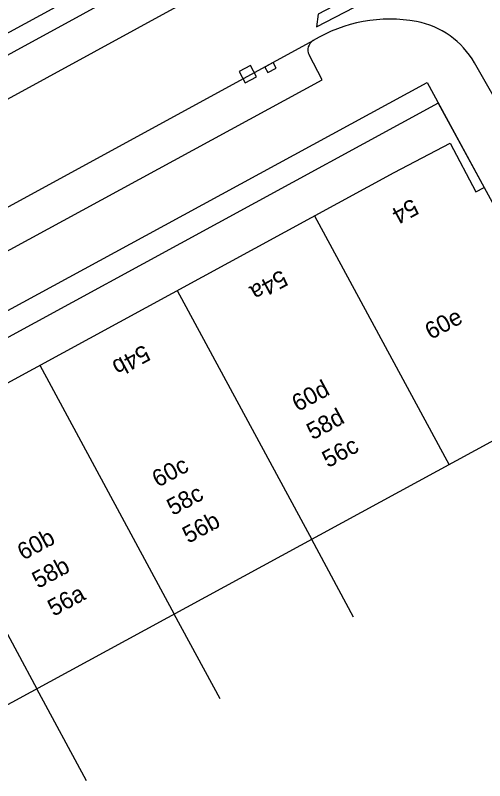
# Model space of a CAD drawing. Extents: x 81065 to 81486, y 452384 to 452681.
# Drawn here: x 81217.68 to 81239.76, y 452440.27 to 452476.31 of the extents above; entities that cross this region are included whole.
import ezdxf

# ---------------------------------------------------------------- set-up
doc = ezdxf.new("R2010")
doc.units = 0
for name, color, linetype in [('B-BH-AL-TOPOGRAFIE_HUISNUMMER-T25', 7, 'Continuous'), ('B-BH-OG-TERREIN_ERF-GV', 7, 'Continuous'), ('B-BH-OG-TOPOGRAFIE_BEBOUWING-GV', 7, 'Continuous'), ('B-BH-OG-TOPOGRAFIE_BEBOUWING_PANDSCHEIDING-GV', 7, 'Continuous'), ('B-BH-RI-GWA_RIOOLPUT-S', 7, 'Continuous'), ('B-BH-VH-KANTOPSLUITING-GV', 7, 'Continuous'), ('B-SRI-KOLK_COMBINATIE-S', 7, 'Continuous'), ('B-WE-VW-MARKERING_DWARS_OVERSTEEK_VOETGANGERS-G', 7, 'Continuous')]:
    doc.layers.add(name, color=color, linetype=linetype)

msp = doc.modelspace()

# ---------------------------------------------------------------- linework, layer by layer
at = {"layer": 'B-BH-OG-TERREIN_ERF-GV'}
for p, q in [((81233.599, 452447.971), (81231.625, 452451.627)), ((81227.315, 452444.118), (81225.16, 452448.11)), ((81221.032, 452440.265), (81218.695, 452444.593))]:
    msp.add_line(p, q, dxfattribs=at)
at = {"layer": 'B-BH-OG-TOPOGRAFIE_BEBOUWING-GV'}
for q in [(81204.716, 452454.266), (81239.739, 452468.204)]:
    msp.add_line((81237.578, 452472.168), q, dxfattribs=at)
for points in [[(81211.96, 452440.929), (81210.814, 452443.005), (81206.534, 452440.655), (81200.066, 452448.769), (81205.913, 452452.053), (81205.606, 452452.621), (81235.506, 452468.904), (81238.146, 452470.28), (81239.352, 452467.994), (81239.739, 452468.204)], [(81239.739, 452468.204), (81244.855, 452458.824)], [(81244.855, 452458.824), (81211.96, 452440.929)]]:
    msp.add_lwpolyline(points, dxfattribs=at)
at = {"layer": 'B-BH-OG-TOPOGRAFIE_BEBOUWING_PANDSCHEIDING-GV'}
for p, q in [((81231.761, 452466.865), (81238.09, 452455.144)), ((81225.298, 452463.345), (81231.625, 452451.627)), ((81218.834, 452459.825), (81225.16, 452448.11)), ((81212.37, 452456.305), (81218.695, 452444.593))]:
    msp.add_line(p, q, dxfattribs=at)
at = {"layer": 'B-BH-RI-GWA_RIOOLPUT-S'}
for p, q in [((81228.743, 452473.942), (81228.207, 452473.656)), ((81229.029, 452473.407), (81228.743, 452473.942)), ((81228.207, 452473.656), (81228.493, 452473.121)), ((81228.493, 452473.121), (81229.029, 452473.407))]:
    msp.add_line(p, q, dxfattribs=at)
at = {"layer": 'B-BH-VH-KANTOPSLUITING-GV'}
msp.add_line((81231.702, 452475.113), (81211.401, 452464.032), dxfattribs=at)
for points in [[(81166.505, 452441.653), (81172.172, 452445.873), (81172.7, 452446.254), (81172.867, 452446.35), (81180.693, 452451.592), (81188.735, 452456.496), (81192.385, 452458.571), (81202.855, 452464.464), (81237.7, 452483.516)], [(81162.668, 452442.441), (81169.895, 452447.714), (81170.064, 452447.811), (81171.72, 452449.007), (81177.948, 452453.188), (81182.8, 452456.219), (81191.033, 452460.983), (81205.552, 452469.075), (81226.775, 452480.625), (81229.065, 452481.856)], [(81228.003, 452478.214), (81227.178, 452479.831), (81204.778, 452467.581), (81194.026, 452461.655), (81191.474, 452460.18), (81186.357, 452457.208), (81179.07, 452452.739), (81171.84, 452447.862), (81171.561, 452447.682), (81164.068, 452442.154)], [(81211.401, 452464.032), (81212.229, 452462.449), (81232.11, 452473.274), (81231.498, 452474.442)], [(81251.327, 452452.997), (81239.284, 452474.068)], [(81186.938, 452440.997), (81186.918, 452441.056), (81185.937, 452443.2), (81185.347, 452444.153), (81191.344, 452447.929), (81190.629, 452449.149), (81194.948, 452451.753), (81202.427, 452455.953), (81205.999, 452457.801), (81206.662, 452456.613), (81223.822, 452465.932), (81237.064, 452473.144), (81239.739, 452468.204)]]:
    msp.add_lwpolyline(points, dxfattribs=at)
for centre, radius, start, end in [((81235.31, 452469.201), 6.926, 79.6375, 121.4006), ((81235.811, 452472.084), 4, 29.7487, 79.2784), ((81231.941, 452474.674), 0.5, 118.6268, 207.6553)]:
    msp.add_arc(centre, radius, start, end, dxfattribs=at)
at = {"layer": 'B-SRI-KOLK_COMBINATIE-S'}
for p, q in [((81229.816, 452474.082), (81229.423, 452473.868)), ((81229.957, 452473.823), (81229.816, 452474.082)), ((81229.423, 452473.868), (81229.564, 452473.609)), ((81229.564, 452473.609), (81229.957, 452473.823))]:
    msp.add_line(p, q, dxfattribs=at)
at = {"layer": 'B-WE-VW-MARKERING_DWARS_OVERSTEEK_VOETGANGERS-G'}
msp.add_lwpolyline([(81235.475, 452478.222), (81231.933, 452476.363), (81231.853, 452475.756), (81235.395, 452477.615)], close=True, dxfattribs=at)

# ---------------------------------------------------------------- texts
at = {"layer": 'B-BH-AL-TOPOGRAFIE_HUISNUMMER-T25'}
for s, rotation, p in [('54', 208.5851, (81236.361, 452467.702)), ('54a', 208.5851, (81230.204, 452464.347)), ('60e', 28.4496, (81237.23, 452461.013)), ('54b', 208.5851, (81223.732, 452460.82)), ('60d', 28.4496, (81230.97, 452457.621)), ('58d', 28.4496, (81231.665, 452456.291)), ('56c', 28.4496, (81232.393, 452454.98)), ('60c', 28.4496, (81224.391, 452454.056)), ('58c', 28.4496, (81225.086, 452452.727)), ('56b', 28.4496, (81225.82, 452451.418)), ('60b', 28.4496, (81218.052, 452450.622)), ('58b', 28.4496, (81218.747, 452449.292)), ('56a', 28.4496, (81219.478, 452447.982))]:
    msp.add_text(s, height=0.8, rotation=rotation, dxfattribs=at).set_placement(p)

doc.saveas('drawing.dxf')
